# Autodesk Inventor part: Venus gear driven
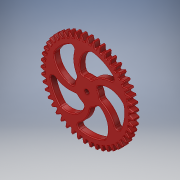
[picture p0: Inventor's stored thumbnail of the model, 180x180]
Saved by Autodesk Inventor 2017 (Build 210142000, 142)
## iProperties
Created: 2016-05
Part Number: Venus gear driven
Material: Generic
Document SubType Name: Modeling
Designer: Stan
Density: 1 g/cm^3
Appearance: Red
Author: Stan
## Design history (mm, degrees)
sketch "Sketch1"
  geometry: A1 r 22.994 centre (38.779, -20.518) between (22.777, -37.029) and (26.428, -39.913); A2 r 22.994 centre (38.779, -20.518) between (22.777, -37.029) and (26.428, -39.913); A3 r 22.994 centre (41.168, -15.166) between (27.509, -33.663) and (31.512, -36.034); A4 r 22.994 centre (41.168, -15.166) between (27.509, -33.663) and (31.512, -36.034); A5 r 22.994 centre (5.209, -43.563) between (27.747, -39.007) and (26.369, -34.563); A6 r 22.994 centre (5.209, -43.563) between (27.747, -39.007) and (26.369, -34.563); A7 r 22.994 centre (42.822, -9.544) between (31.75, -29.696) and (36.034, -31.512); A8 r 22.994 centre (42.822, -9.544) between (31.75, -29.696) and (36.034, -31.512); A9 r 22.994 centre (10.969, -42.479) between (32.699, -34.961) and (30.74, -30.74); A10 r 22.994 centre (10.969, -42.479) between (32.699, -34.961) and (30.74, -30.74); A11 r 22.994 centre (43.712, -3.751) between (35.425, -25.199) and (39.913, -26.428); A12 r 22.994 centre (43.712, -3.751) between (35.425, -25.199) and (39.913, -26.428); A13 r 22.994 centre (16.533, -40.638) between (37.067, -30.291) and (34.563, -26.369); A14 r 22.994 centre (16.533, -40.638) between (37.067, -30.291) and (34.563, -26.369); A15 r 22.994 centre (14.998, 41.23) between (-7.172, 47.329) and (-7.946, 42.741); A16 r 22.994 centre (-29.903, 32.103) between (-9.37, 42.451) and (-11.874, 46.373); A17 r 22.994 centre (9.368, 42.861) between (-13.417, 45.951) and (-13.572, 41.3); A18 r 22.994 centre (-33.915, 27.831) between (-14.944, 40.824) and (-17.949, 44.377); A19 r 22.994 centre (3.572, 43.727) between (-19.421, 43.752) and (-18.956, 39.123); A20 r 22.994 centre (-37.322, 23.062) between (-20.252, 38.467) and (-23.703, 41.589); A21 r 22.994 centre (-2.288, 43.813) between (-25.08, 40.773) and (-24.001, 36.247); A22 r 22.994 centre (-40.063, 17.882) between (-25.199, 35.425) and (-29.035, 38.058); A23 r 22.994 centre (-8.107, 43.117) between (-30.291, 37.067) and (-28.618, 32.725); A24 r 22.994 centre (-42.089, 12.383) between (-29.696, 31.75) and (-33.849, 33.849); A25 r 22.994 centre (-13.782, 41.652) between (-34.961, 32.699) and (-32.725, 28.618); A26 r 22.994 centre (-43.364, 6.662) between (-33.663, 27.509) and (-38.058, 29.035); A27 r 22.994 centre (-19.211, 39.443) between (-39.007, 27.747) and (-36.247, 24.001); A28 r 22.994 centre (-43.865, 0.823) between (-37.029, 22.777) and (-41.589, 23.703); A29 r 22.994 centre (-24.297, 36.531) between (-42.357, 22.3) and (-39.123, 18.956); A30 r 22.994 centre (-43.583, -5.031) between (-39.734, 17.638) and (-44.377, 17.949); A31 r 22.994 centre (-28.949, 32.967) between (-44.952, 16.456) and (-41.3, 13.572); A32 r 22.994 centre (-42.524, -10.795) between (-41.731, 12.184) and (-46.373, 11.874); A33 r 22.994 centre (-33.085, 28.814) between (-46.744, 10.317) and (-42.741, 7.946); A34 r 22.994 centre (-40.706, -16.367) between (-42.982, 6.514) and (-47.542, 5.587); A35 r 22.994 centre (-36.63, 24.147) between (-47.702, 3.995) and (-43.418, 2.178); A36 r 22.994 centre (-38.161, -21.646) between (-43.467, 0.726) and (-47.863, -0.8); A37 r 22.994 centre (-39.522, 19.049) between (-47.809, -2.399) and (-43.321, -3.628); A38 r 22.994 centre (-34.935, -26.54) between (-43.176, -5.074) and (-47.329, -7.172); A39 r 22.994 centre (-41.708, 13.612) between (-47.063, -8.75) and (-42.451, -9.37); A40 r 22.994 centre (-31.086, -30.959) between (-42.115, -10.783) and (-45.951, -13.417); A41 r 22.994 centre (-43.15, 7.931) between (-45.477, -14.944) and (-40.824, -14.944); A42 r 22.994 centre (-26.682, -34.826) between (-40.301, -16.3) and (-43.752, -19.421); A43 r 22.994 centre (-43.822, 2.109) between (-43.079, -20.873) and (-38.467, -20.252); A44 r 22.994 centre (-21.802, -38.072) between (-37.769, -21.526) and (-40.773, -25.08); A45 r 22.994 centre (-43.712, -3.751) between (-39.913, -26.428) and (-35.425, -25.199); A46 r 22.994 centre (-16.533, -40.638) between (-34.563, -26.369) and (-37.067, -30.291); A47 r 22.994 centre (-42.822, -9.544) between (-36.034, -31.512) and (-31.75, -29.696); A48 r 22.994 centre (-10.969, -42.479) between (-30.74, -30.74) and (-32.699, -34.961); A49 r 22.994 centre (-41.168, -15.166) between (-31.512, -36.034) and (-27.509, -33.663); A50 r 22.994 centre (-5.209, -43.563) between (-26.369, -34.563) and (-27.747, -39.007); A51 r 22.994 centre (-38.779, -20.518) between (-26.428, -39.913) and (-22.777, -37.029); A52 r 22.994 centre (0.643, -43.868) between (-21.526, -37.769) and (-22.3, -42.357); A53 r 22.994 centre (-35.699, -25.504) between (-20.873, -43.079) and (-17.638, -39.734); A54 r 22.994 centre (6.485, -43.391) between (-16.3, -40.301) and (-16.456, -44.952); A55 r 22.994 centre (-31.981, -30.034) between (-14.944, -45.477) and (-12.184, -41.731); A56 r 22.994 centre (12.21, -42.14) between (-10.783, -42.115) and (-10.317, -46.744); A57 r 22.994 centre (-27.692, -34.029) between (-8.75, -47.063) and (-6.514, -42.982); A58 r 22.994 centre (17.718, -40.136) between (-5.074, -43.176) and (-3.995, -47.702); A59 r 22.994 centre (-22.91, -37.416) between (-2.399, -47.809) and (-0.726, -43.467); A60 r 22.994 centre (22.91, -37.416) between (0.726, -43.467) and (2.399, -47.809); A61 r 22.994 centre (-17.718, -40.136) between (3.995, -47.702) and (5.074, -43.176); A62 r 22.994 centre (27.692, -34.029) between (6.514, -42.982) and (8.75, -47.063); A63 r 22.994 centre (-12.21, -42.14) between (10.317, -46.744) and (10.783, -42.115); A64 r 22.994 centre (31.981, -30.034) between (12.184, -41.731) and (14.944, -45.477)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; 1 further point
  constraints: 404 point on circle, 202 centre point, 4 horizontal alignment, 602 other
  dimensions: "d0" = 0 dimension on point (0, 0); "d1" = 0 dimension on point (0, 0)
extrude "Extrusion1" new body sketch "Sketch1" distance "d2" = 6.35; taper "d3" = 0 deg
sketch "Sketch2"
  geometry: A1 r 38.1 centre (0, 0) between (29.793, -23.749) and (37.436, 7.083); A2 r 38.1 centre (0, 0) between (31.793, 20.996) and (4.832, 37.792); A3 r 38.1 centre (0, 0) between (-10.144, 36.725) and (-33.689, 17.796); A4 r 38.1 centre (0, 0) between (-38.062, 1.701) and (-27.335, -26.541); A5 r 38.1 centre (0, 0) between (-15.079, -34.989) and (18.305, -33.415); A6 r 26.136 centre (11.787, 22.509) between (-10.144, 36.725) and (-9.912, 7.941); A7 r 19.198 centre (11.761, 19.889) between (4.832, 37.792) and (-5.485, 11.455); A8 r 26.136 centre (-17.765, 18.166) between (-38.062, 1.701) and (-10.615, -6.973); A9 r 19.198 centre (-14.494, 17.427) between (-33.689, 17.796) and (-12.589, -1.677); A10 r 26.136 centre (-22.686, -9.985) between (-15.079, -34.989) and (3.351, -12.25); A11 r 19.198 centre (-21.053, -8.4) between (-27.335, -26.541) and (-2.295, -12.491); A12 r 26.136 centre (3.694, -25.138) between (29.793, -23.749) and (12.686, -0.598); A13 r 19.198 centre (2.175, -23.003) between (18.305, -33.415) and (11.17, -6.043); A14 r 26.136 centre (25.05, -4.255) between (31.793, 20.996) and (4.489, 11.88); A15 r 19.198 centre (22.55, -5.04) between (37.436, 7.083) and (9.199, 8.756); A16 r 12.7 centre (0, 0) between (4.489, 11.88) and (-5.485, 11.455); A17 r 12.7 centre (0, 0) between (12.686, -0.598) and (9.199, 8.756); A18 r 12.7 centre (0, 0) between (3.351, -12.25) and (11.17, -6.043); A19 r 12.7 centre (0, 0) between (-9.912, 7.941) and (-12.589, -1.677); A20 r 12.7 centre (0, 0) between (-10.615, -6.973) and (-2.295, -12.491); 1 further point
  constraints: 40 point on circle, 20 centre point
  dimensions: "d4" = 0 distance of point (0, 0) A1.centre; "d5" = 0 distance of point (0, 0) A1.centre; "d6" = 12.7 radius of A16; "d7" = 12.7 radius of A17; "d8" = 12.7 radius of A18; "d9" = 12.7 radius of A20; "d10" = 12.7 radius of A19; "d11" = 38.1 radius of A2; "d12" = 38.1 radius of A3; "d13" = 38.1 radius of A4; "d14" = 38.1 radius of A5; "d15" = 38.1 radius of A1
extrude "Extrusion2" cut sketch "Sketch2" distance "d16" = 6.35; taper "d17" = 0 deg
sketch "Sketch3"
  geometry: C1 r 2.381 at (0, 0); 1 further point
  constraints: 1 centre point, 1 coincident
  dimensions: "d18" = 4.7625 diameter of C1
fillet "Fillet1" dims "d19" = 3.175
extrude "Extrusion3" cut sketch "Sketch3" distance "d20" = 6.35; taper "d21" = 0 deg
fillet "Fillet2" dims "d22" = 0.79375
fillet "Fillet3" dims "d23" = 0.762
fillet "Fillet4" dims "d24" = 0.762
fillet "Fillet5" dims "d25" = 0.762
fillet "Fillet6" dims "d26" = 0.762
fillet "Fillet7" dims "d27" = 0.79375
body "Solid1"
